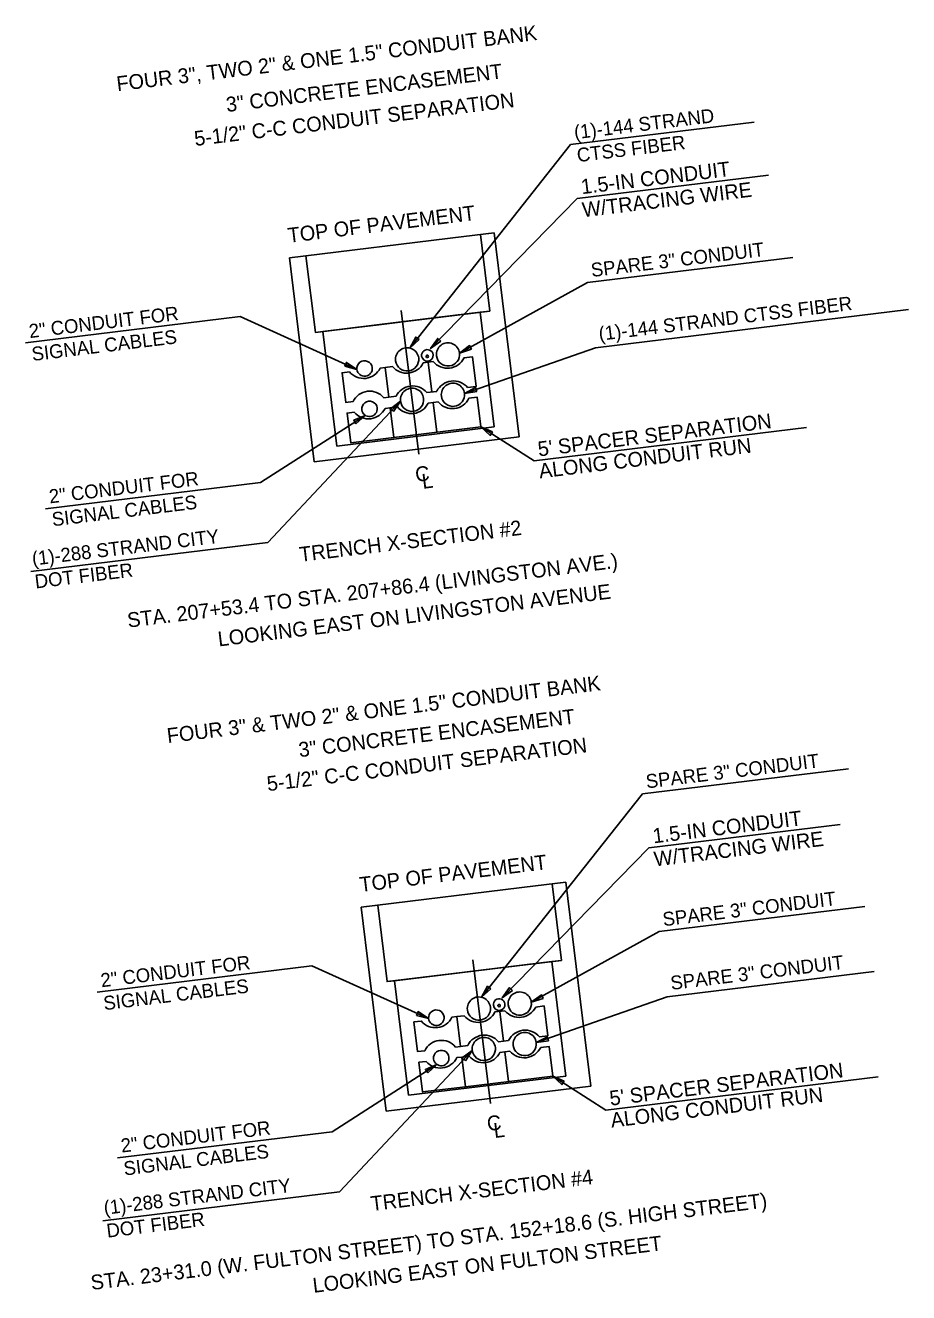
# Model space of a CAD drawing. Extents: x 91401 to 1830080, y 35587 to 712188.
# Drawn here: x 1827406 to 1827763, y 711374 to 711887 of the extents above; entities that cross this region are included whole.
import ezdxf

# ---------------------------------------------------------------- set-up
doc = ezdxf.new("R2010")
doc.units = 0
doc.layers.add('Default', color=7, linetype='Continuous')
doc.layers.add('SH_Text', color=7, linetype='Continuous')

# ---------------------------------------------------------------- blocks, each defined once
blk = doc.blocks.new('POINT_DISPLAY')
at = {"layer": 'Default'}
blk.add_line((0, 0), (0, 0), dxfattribs=at)

msp = doc.modelspace()

# ---------------------------------------------------------------- linework, layer by layer
at = {"layer": 'SH_Text'}
for p, q in [((1827626.3, 711838.45), (1827700.57, 711847.52)), ((1827561.22, 711756.14), (1827626.3, 711838.45)), ((1827628.96, 711816.65), (1827706.33, 711826.1)), ((1827569.64, 711755.94), (1827628.96, 711816.65)), ((1827595.38, 711802.72), (1827589.79, 711802.04)), ((1827593.57, 711771.08), (1827589.79, 711802.04)), ((1827605.45, 711720.2), (1827595.38, 711802.72)), ((1827519.25, 711793.42), (1827512.54, 711792.6)), ((1827512.54, 711792.6), (1827522.62, 711710.08)), ((1827523.03, 711762.47), (1827519.25, 711793.42)), ((1827633.1, 711782.7), (1827716.23, 711792.85)), ((1827581.36, 711754.15), (1827633.1, 711782.7)), ((1827557.75, 711771.29), (1827564.84, 711713.21)), ((1827589.73, 711770.61), (1827595.38, 711724.29)), ((1827636.33, 711756.29), (1827763.01, 711771.76)), ((1827405.73, 711758.26), (1827492.64, 711768.87)), ((1827539.83, 711747.5), (1827492.64, 711768.87)), ((1827526.01, 711762.83), (1827523.03, 711762.47)), ((1827531.66, 711716.51), (1827526.01, 711762.83)), ((1827583.36, 711737.81), (1827636.33, 711756.29)), ((1827557.49, 711734.65), (1827503.8, 711677.45)), ((1827543.21, 711728.93), (1827500.83, 711701.72)), ((1827531.66, 711716.51), (1827595.38, 711724.29)), ((1827531.66, 711716.51), (1827595.38, 711724.29)), ((1827531.66, 711716.51), (1827595.38, 711724.29)), ((1827531.66, 711716.51), (1827595.38, 711724.29)), ((1827595.38, 711724.29), (1827531.66, 711716.51)), ((1827590.01, 711724.24), (1827611.5, 711710.52)), ((1827611.5, 711710.52), (1827721.71, 711723.98)), ((1827522.62, 711710.08), (1827605.45, 711720.2)), ((1827522.62, 711710.08), (1827605.45, 711720.2)), ((1827413.93, 711691.11), (1827500.83, 711701.72)), ((1827407.98, 711665.75), (1827503.8, 711677.45)), ((1827655.32, 711575.8), (1827738.69, 711585.98)), ((1827590.24, 711493.49), (1827655.32, 711575.8)), ((1827657.98, 711554), (1827735.35, 711563.45)), ((1827598.66, 711493.3), (1827657.98, 711554)), ((1827624.4, 711540.07), (1827618.81, 711539.39)), ((1827622.59, 711508.43), (1827618.81, 711539.39)), ((1827634.48, 711457.55), (1827624.4, 711540.07)), ((1827548.27, 711530.78), (1827541.56, 711529.96)), ((1827541.56, 711529.96), (1827551.64, 711447.43)), ((1827552.05, 711499.82), (1827548.27, 711530.78)), ((1827662.13, 711520.06), (1827745.26, 711530.21)), ((1827610.39, 711491.5), (1827662.13, 711520.06)), ((1827586.77, 711508.64), (1827593.86, 711450.56)), ((1827618.75, 711507.96), (1827624.41, 711461.64)), ((1827434.76, 711495.61), (1827521.66, 711506.22)), ((1827568.86, 711484.86), (1827521.66, 711506.22)), ((1827665.35, 711493.64), (1827749.02, 711503.86)), ((1827555.03, 711500.18), (1827552.05, 711499.82)), ((1827560.69, 711453.86), (1827555.03, 711500.18)), ((1827612.38, 711475.16), (1827665.35, 711493.64)), ((1827586.51, 711472.01), (1827532.82, 711414.8)), ((1827572.23, 711466.29), (1827529.86, 711439.08)), ((1827560.69, 711453.86), (1827624.41, 711461.64)), ((1827560.69, 711453.86), (1827624.41, 711461.64)), ((1827560.69, 711453.86), (1827624.41, 711461.64)), ((1827560.69, 711453.86), (1827624.41, 711461.64)), ((1827624.41, 711461.64), (1827560.69, 711453.86)), ((1827619.03, 711461.6), (1827640.53, 711447.87)), ((1827551.64, 711447.43), (1827634.48, 711457.55)), ((1827551.64, 711447.43), (1827634.48, 711457.55)), ((1827640.53, 711447.87), (1827750.73, 711461.33)), ((1827442.96, 711428.47), (1827529.86, 711439.08)), ((1827437.01, 711403.1), (1827532.82, 711414.8))]:
    msp.add_line(p, q, dxfattribs=at)
for points in [[(1827512.54, 711792.6), (1827583.08, 711801.22), (1827595.38, 711802.72), (1827595.38, 711802.72)], [(1827519.25, 711793.42), (1827523.03, 711762.47), (1827593.57, 711771.08), (1827589.79, 711802.04)], [(1827589.79, 711802.04), (1827593.57, 711771.08), (1827589.73, 711770.61)], [(1827605.45, 711720.2), (1827595.38, 711802.72)], [(1827522.62, 711710.08), (1827512.54, 711792.6)], [(1827526.01, 711762.83), (1827566.57, 711767.78), (1827589.73, 711770.61), (1827595.38, 711724.29)], [(1827526.01, 711762.83), (1827566.57, 711767.78), (1827589.73, 711770.61), (1827595.38, 711724.29)], [(1827526.01, 711762.83), (1827584.38, 711769.96), (1827589.73, 711770.61), (1827595.38, 711724.29)], [(1827526.01, 711762.83), (1827548.76, 711765.61), (1827589.73, 711770.61), (1827595.38, 711724.29)], [(1827531.66, 711716.51), (1827526.01, 711762.83)], [(1827531.66, 711716.51), (1827526.01, 711762.83)], [(1827554.2, 711748.66), (1827551.28, 711748.31), (1827552.75, 711736.27)], [(1827570.71, 711750.68), (1827566.65, 711750.18)], [(1827568.68, 711750.43), (1827570.15, 711738.39)], [(1827584.63, 711740.16), (1827588.02, 711740.57), (1827586.55, 711752.61), (1827583.16, 711752.2)], [(1827536.8, 711746.54), (1827533.88, 711746.18), (1827535.35, 711734.14), (1827538.27, 711734.5)], [(1827551.28, 711748.31), (1827549.25, 711748.06)], [(1827568.12, 711738.15), (1827572.18, 711738.64)], [(1827550.72, 711736.02), (1827552.75, 711736.27)], [(1827552.75, 711736.27), (1827555.67, 711736.62)], [(1827554.74, 711719.94), (1827590.01, 711724.24), (1827588.54, 711736.28), (1827585.15, 711735.87)], [(1827572.7, 711734.35), (1827568.65, 711733.85)], [(1827570.68, 711734.1), (1827572.15, 711722.06)], [(1827538.8, 711730.21), (1827535.87, 711729.85), (1827537.34, 711717.81), (1827554.74, 711719.94)], [(1827553.27, 711731.97), (1827551.25, 711731.73)], [(1827556.2, 711732.33), (1827553.27, 711731.97), (1827554.74, 711719.94)], [(1827541.56, 711529.96), (1827612.11, 711538.57), (1827624.4, 711540.07), (1827624.4, 711540.07)], [(1827548.27, 711530.78), (1827552.05, 711499.82), (1827622.59, 711508.43), (1827618.81, 711539.39)], [(1827618.81, 711539.39), (1827622.59, 711508.43), (1827618.75, 711507.96)], [(1827634.48, 711457.55), (1827624.4, 711540.07)], [(1827551.64, 711447.43), (1827541.56, 711529.96)], [(1827555.03, 711500.18), (1827595.59, 711505.14), (1827618.75, 711507.96), (1827624.41, 711461.64)], [(1827555.03, 711500.18), (1827595.59, 711505.14), (1827618.75, 711507.96), (1827624.41, 711461.64)], [(1827555.03, 711500.18), (1827613.41, 711507.31), (1827618.75, 711507.96), (1827624.41, 711461.64)], [(1827555.03, 711500.18), (1827577.78, 711502.96), (1827618.75, 711507.96), (1827624.41, 711461.64)], [(1827560.69, 711453.86), (1827555.03, 711500.18)], [(1827560.69, 711453.86), (1827555.03, 711500.18)], [(1827599.73, 711488.03), (1827595.68, 711487.54)], [(1827597.71, 711487.78), (1827599.17, 711475.75)], [(1827613.65, 711477.51), (1827617.04, 711477.93), (1827615.57, 711489.97), (1827612.18, 711489.55)], [(1827565.83, 711483.89), (1827562.9, 711483.53), (1827564.37, 711471.5), (1827567.3, 711471.85)], [(1827580.3, 711485.66), (1827578.28, 711485.41)], [(1827583.23, 711486.02), (1827580.3, 711485.66), (1827581.77, 711473.62)], [(1827579.75, 711473.37), (1827581.77, 711473.62)], [(1827581.77, 711473.62), (1827584.7, 711473.98)], [(1827583.77, 711457.29), (1827619.03, 711461.6), (1827617.56, 711473.63), (1827614.18, 711473.22)], [(1827597.15, 711475.5), (1827601.2, 711475.99)], [(1827601.73, 711471.7), (1827597.67, 711471.21)], [(1827567.82, 711467.56), (1827564.9, 711467.2), (1827566.37, 711455.17), (1827583.77, 711457.29)], [(1827582.3, 711469.33), (1827580.27, 711469.08)], [(1827585.22, 711469.69), (1827582.3, 711469.33), (1827583.77, 711457.29)], [(1827599.7, 711471.45), (1827601.17, 711459.42)]]:
    msp.add_lwpolyline(points, dxfattribs=at)
for points in [[(1827564.97, 711759.55), (1827563.67, 711760.58), (1827561.22, 711756.14)], [(1827573.75, 711758.9), (1827572.57, 711760.08), (1827569.64, 711755.94)], [(1827586.2, 711755.67), (1827585.44, 711757.16), (1827581.36, 711754.15)], [(1827534.93, 711748.8), (1827535.62, 711750.32), (1827539.83, 711747.5)], [(1827588.37, 711738.55), (1827587.86, 711740.14), (1827583.36, 711737.81)], [(1827554.67, 711730.44), (1827553.46, 711731.58), (1827557.49, 711734.65)], [(1827539.45, 711725.53), (1827538.55, 711726.93), (1827543.21, 711728.93)], [(1827594.67, 711722.25), (1827593.77, 711720.84), (1827590.01, 711724.24)], [(1827594, 711496.9), (1827592.69, 711497.93), (1827590.24, 711493.49)], [(1827602.77, 711496.26), (1827601.59, 711497.43), (1827598.66, 711493.3)], [(1827615.22, 711493.03), (1827614.47, 711494.51), (1827610.39, 711491.5)], [(1827563.96, 711486.16), (1827564.65, 711487.68), (1827568.86, 711484.86)], [(1827617.4, 711475.91), (1827616.88, 711477.49), (1827612.38, 711475.16)], [(1827583.7, 711467.79), (1827582.48, 711468.93), (1827586.51, 711472.01)], [(1827568.47, 711462.88), (1827567.57, 711464.28), (1827572.23, 711466.29)], [(1827623.69, 711459.6), (1827622.79, 711458.2), (1827619.03, 711461.6)]]:
    msp.add_lwpolyline(points, close=True, dxfattribs=at)
for centre, radius, start, end in [((1827560.16, 711751.56), 4.7, 6.9614, 186.9614), ((1827568.35, 711753.17), 2.35, 6.9614, 186.9614), ((1827576.7, 711753.58), 4.7, 6.9614, 186.9614), ((1827576.7, 711753.58), 4.7, 186.9614, 6.9614), ((1827542.94, 711747.88), 3.13, 6.9614, 186.9614), ((1827559.94, 711753.42), 7.45, 219.6485, 334.2743), ((1827560.16, 711751.56), 4.7, 186.9614, 6.9614), ((1827568.35, 711753.17), 2.35, 186.9614, 6.9614), ((1827568.33, 711752.76), 0.5, 6.9614, 186.9614), ((1827568.33, 711752.76), 0.5, 186.9614, 6.9614), ((1827576.45, 711755.43), 7.45, 219.6485, 334.2743), ((1827542.54, 711751.29), 7.45, 219.6485, 334.2743), ((1827542.94, 711747.88), 3.13, 186.9614, 6.9614), ((1827544.98, 711731.27), 7.45, 39.6485, 154.2743), ((1827562.39, 711733.39), 7.45, 39.6485, 154.2743), ((1827562.15, 711735.22), 4.7, 6.9614, 186.9614), ((1827578.89, 711735.41), 7.45, 39.6485, 154.2743), ((1827578.69, 711737.24), 4.7, 6.9614, 186.9614), ((1827544.94, 711731.54), 3.13, 6.9614, 186.9614), ((1827561.94, 711737.09), 7.45, 219.6485, 334.2743), ((1827562.15, 711735.22), 4.7, 186.9614, 6.9614), ((1827578.44, 711739.1), 7.45, 219.6485, 334.2743), ((1827578.69, 711737.24), 4.7, 186.9614, 6.9614), ((1827544.53, 711734.96), 7.45, 219.6485, 334.2743), ((1827544.94, 711731.54), 3.13, 186.9614, 6.9614), ((1827589.18, 711488.92), 4.7, 6.9614, 186.9614), ((1827597.38, 711490.52), 2.35, 6.9614, 186.9614), ((1827605.72, 711490.94), 4.7, 6.9614, 186.9614), ((1827571.97, 711485.24), 3.13, 6.9614, 186.9614), ((1827588.97, 711490.77), 7.45, 219.6485, 334.2743), ((1827589.18, 711488.92), 4.7, 186.9614, 6.9614), ((1827597.38, 711490.52), 2.35, 186.9614, 6.9614), ((1827597.36, 711490.11), 0.5, 6.9614, 186.9614), ((1827597.36, 711490.11), 0.5, 186.9614, 6.9614), ((1827605.47, 711492.79), 7.45, 219.6485, 334.2743), ((1827605.72, 711490.94), 4.7, 186.9614, 6.9614), ((1827571.56, 711488.65), 7.45, 219.6485, 334.2743), ((1827571.97, 711485.24), 3.13, 186.9614, 6.9614), ((1827591.41, 711470.74), 7.45, 39.6485, 154.2743), ((1827591.17, 711472.58), 4.7, 6.9614, 186.9614), ((1827607.91, 711472.76), 7.45, 39.6485, 154.2743), ((1827607.72, 711474.59), 4.7, 6.9614, 186.9614), ((1827574.01, 711468.62), 7.45, 39.6485, 154.2743), ((1827573.96, 711468.9), 3.13, 6.9614, 186.9614), ((1827591.17, 711472.58), 4.7, 186.9614, 6.9614), ((1827607.46, 711476.45), 7.45, 219.6485, 334.2743), ((1827607.72, 711474.59), 4.7, 186.9614, 6.9614), ((1827573.56, 711472.32), 7.45, 219.6485, 334.2743), ((1827573.96, 711468.9), 3.13, 186.9614, 6.9614), ((1827590.96, 711474.44), 7.45, 219.6485, 334.2743)]:
    msp.add_arc(centre, radius, start, end, dxfattribs=at)

# ---------------------------------------------------------------- block references
at = {"layer": 'SH_Text', "xscale": 1.5748, "yscale": 1.5748000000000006, "rotation": 6.96142799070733}
for p in [(1827564, 711720.06), (1827593.03, 711457.42)]:
    msp.add_blockref('POINT_DISPLAY', p, dxfattribs=at)

# ---------------------------------------------------------------- texts
at = {"layer": 'SH_Text'}
for s, height, p in [('FOUR 3", TWO 2" & ONE 1.5" CONDUIT BANK', 6, (1827442.99, 711860.05)), ('3" CONCRETE ENCASEMENT', 6, (1827487.25, 711851.64)), ('5-1/2" C-C CONDUIT SEPARATION', 6, (1827474.43, 711837.88)), ('(1)-144 STRAND', 5.6, (1827628.04, 711840.62)), ('CTSS FIBER', 5.6, (1827629.17, 711831.36)), ('1.5-IN CONDUIT', 6, (1827630.84, 711818.4)), ('W/TRACING WIRE', 6, (1827631.34, 711809.06)), ('TOP OF PAVEMENT', 6, (1827512.25, 711798.72)), ('SPARE 3" CONDUIT', 5.6, (1827634.85, 711784.88)), ('(1)-144 STRAND CTSS FIBER', 5.6, (1827637.99, 711759.09)), ('2" CONDUIT FOR ', 5.6, (1827407.51, 711760.16)), ('SIGNAL CABLES', 5.6, (1827408.64, 711750.9)), ("5' SPACER SEPARATION", 6, (1827613.38, 711712.28)), ('ALONG CONDUIT RUN', 6, (1827613.83, 711703.4)), ('C', 6, (1827563.79, 711701.97)), ('2" CONDUIT FOR ', 5.6, (1827415.67, 711693.29)), ('L', 6, (1827566.49, 711699.18)), ('SIGNAL CABLES', 5.6, (1827416.81, 711684.02)), ('(1)-288 STRAND CITY ', 5.6, (1827408.77, 711668.12)), ('TRENCH X-SECTION #2', 6, (1827516.91, 711669.63)), ('STA. 207+53.4 TO STA. 207+86.4 (LIVINGSTON AVE.)', 6, (1827447.34, 711643.03)), ('DOT FIBER', 5.6, (1827409.9, 711658.86)), ('LOOKING EAST ON LIVINGSTON AVENUE', 6, (1827483.96, 711635.41)), ('FOUR 3" & TWO 2" & ONE 1.5" CONDUIT BANK', 6, (1827463.37, 711596.32)), ('3" CONCRETE ENCASEMENT', 6, (1827516.62, 711590.62)), ('5-1/2" C-C CONDUIT SEPARATION', 6, (1827503.8, 711576.86)), ('SPARE 3" CONDUIT', 5.6, (1827657.06, 711577.98)), ('1.5-IN CONDUIT', 6, (1827659.86, 711555.76)), ('W/TRACING WIRE', 6, (1827660.36, 711546.41)), ('TOP OF PAVEMENT', 6, (1827541.27, 711536.08)), ('SPARE 3" CONDUIT', 5.6, (1827663.87, 711522.23)), ('2" CONDUIT FOR ', 5.6, (1827436.53, 711497.52)), ('SPARE 3" CONDUIT', 5.6, (1827667.02, 711496.45)), ('SIGNAL CABLES', 5.6, (1827437.66, 711488.25)), ("5' SPACER SEPARATION", 6, (1827642.41, 711449.63)), ('ALONG CONDUIT RUN', 6, (1827642.85, 711440.75)), ('2" CONDUIT FOR ', 5.6, (1827444.7, 711430.64)), ('C', 6, (1827592.82, 711439.32)), ('L', 6, (1827595.51, 711436.53)), ('SIGNAL CABLES', 5.6, (1827445.83, 711421.37)), ('TRENCH X-SECTION #4', 6, (1827545.79, 711406.96)), ('(1)-288 STRAND CITY ', 5.6, (1827437.79, 711405.48)), ('STA. 23+31.0 (W. FULTON STREET) TO STA. 152+18.6 (S. HIGH STREET)', 6, (1827432.54, 711375.04)), ('DOT FIBER', 5.6, (1827438.92, 711396.21)), ('LOOKING EAST ON FULTON STREET', 6, (1827522.34, 711373.91))]:
    msp.add_text(s, height=height, rotation=6.9614, dxfattribs=at).set_placement(p)

doc.saveas('drawing.dxf')
